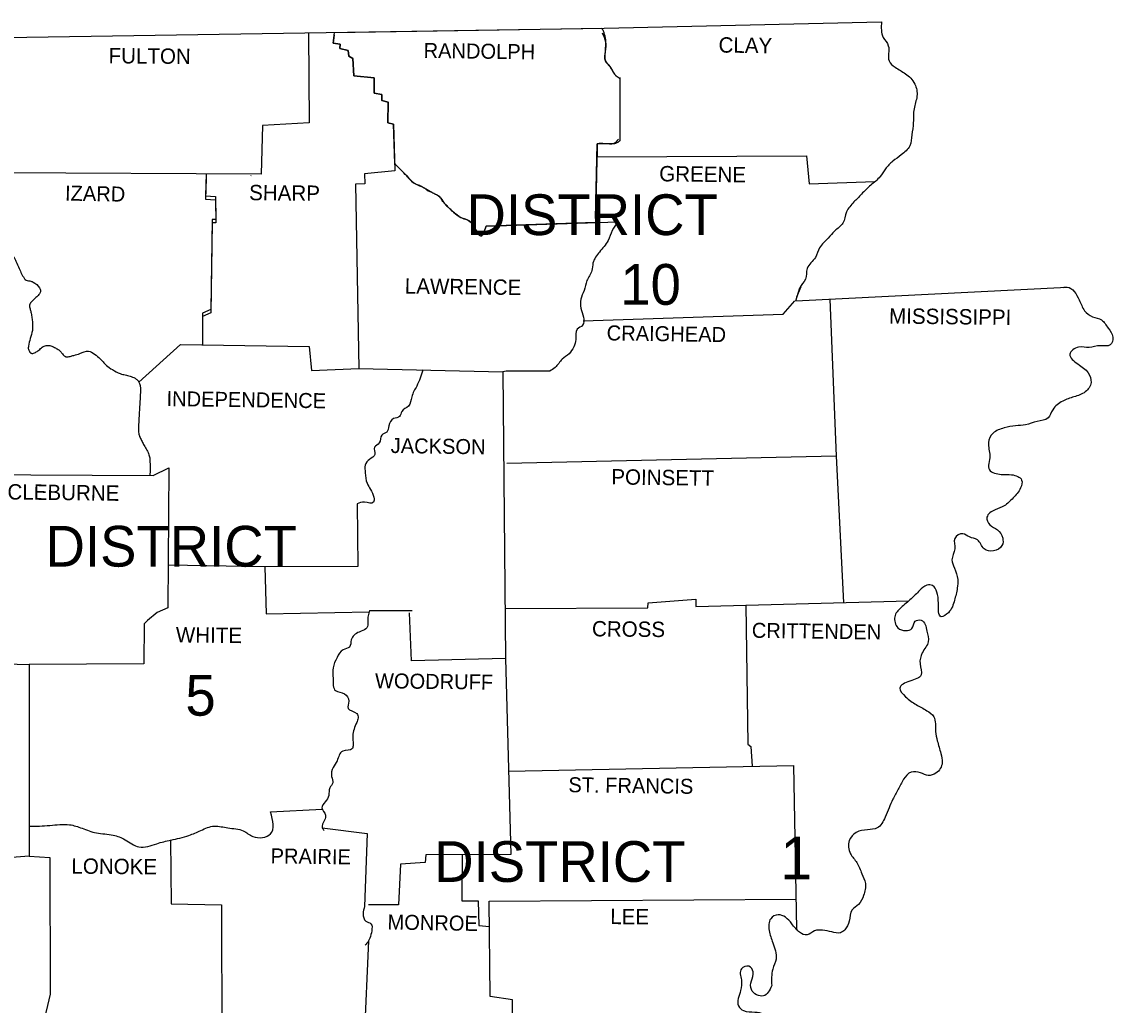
# Model space of a CAD drawing. Extents: x 3046 to 131673, y -8885 to 10756.
# Drawn here: x 28781 to 31768, y 7667 to 10358 of the extents above; entities that cross this region are included whole.
import ezdxf

# ---------------------------------------------------------------- set-up
doc = ezdxf.new("R2010")
doc.units = 0
for name, color, linetype in [('1', 7, 'Continuous'), ('2', 7, 'Continuous'), ('3', 7, 'Continuous')]:
    doc.layers.add(name, color=color, linetype=linetype)

msp = doc.modelspace()

# ---------------------------------------------------------------- linework, layer by layer
at = {"layer": '1'}
for p, q in [((29636.5, 10328.9), (30368.7, 10340.3)), ((30417.5, 10202.4), (30417.5, 10032.6)), ((30898.8, 9593.9), (30910.6, 9630.1)), ((30901.8, 9605.6), (30913.5, 9634)), ((29732.6, 8746.6), (29849, 8746.6))]:
    msp.add_line(p, q, dxfattribs=at)
for points in [[(25766.1, 10313), (27348.2, 10312), (28736.6, 10314.9), (30374.4, 10340.4), (31133.7, 10358)], [(28736.6, 10309.1), (28738.5, 10076.2), (28721.9, 10075.2), (28724.8, 9831.6), (28656.3, 9821.8), (28662.2, 9756.3), (28685.7, 9725.9), (28683.7, 9648.7), (28550.7, 9643.8), (28545.8, 9524.4), (28424.5, 9520.5), (28418.6, 9375.7), (28425.4, 9363.9), (28428.4, 9133), (28637.7, 9119.3), (28634.8, 8603.7), (28801.1, 8598.8), (28801.1, 8074.4), (28670, 8064.6), (28660.3, 7949.2), (28440.1, 7948.2)], [(29565.2, 10327.8), (29567.2, 10081.1), (29440, 10074.3), (29436.1, 9941.2), (28723.5, 9945.1)], [(29801.4, 9970.4), (29798.1, 10078.2), (29782.5, 10081.1), (29783.5, 10137.9), (29765.9, 10142.7), (29765.9, 10159.4), (29745.3, 10162.3), (29745.3, 10204.4), (29689.5, 10210.3), (29686.6, 10257.2), (29675.8, 10264.1), (29673.9, 10279.7), (29651.4, 10284.6), (29652.4, 10296.4), (29632.8, 10299.3), (29636.5, 10328.9)], [(29635.7, 10322.8), (29632.8, 10299.3), (29652.4, 10296.4), (29651.4, 10284.6), (29673.9, 10279.7), (29675.8, 10264.1), (29686.6, 10257.2), (29689.5, 10210.3), (29745.3, 10204.4), (29745.3, 10162.3), (29765.9, 10159.4), (29765.9, 10142.7), (29783.5, 10137.9), (29782.5, 10081.1), (29798.1, 10078.2), (29802.1, 9950), (29718.9, 9942.2), (29719.9, 9914.8), (29694.4, 9913.8), (29703.2, 9408.9), (30097.5, 9400.1), (30104.4, 8615.5), (29847.1, 8608.6), (29842.2, 8740.7)], [(30417.5, 10205.4), (30417.5, 10040)], [(30355.8, 10024.4), (30350.7, 9808.8), (30051.5, 9798.3)], [(30350.9, 9819.9), (30355.8, 10024.4), (30355.8, 9988.2), (30928.2, 9991.1), (30936, 9914.8), (31115.6, 9921.3)], [(29285.6, 9942), (29283.5, 9881.5), (29310.9, 9879.6), (29311.9, 9816.9), (29302.1, 9816.9), (29298.2, 9570.4), (29275.7, 9560.6), (29275.7, 9478.4)], [(29285.5, 9929.5), (29283.5, 9872.7), (29310.9, 9870.7), (29311.9, 9808.1), (29302.1, 9808.1), (29298.2, 9561.6), (29275.7, 9551.8), (29275.7, 9473.7)], [(29407.8, 9936.3), (29408.7, 9937.3)], [(30051.5, 9798.3), (30412.2, 9811)], [(30898.8, 9593.9), (31641.5, 9632)], [(30316.8, 9539.9), (30864.6, 9557.7), (30896.9, 9594.8)], [(30992.5, 9598.7), (31009.4, 9169.2), (31029.3, 8768.4)], [(29101.4, 9371.9), (29215, 9474.5), (29567.2, 9469.6), (29574.1, 9404), (29703.2, 9409)], [(30225.7, 9402.1), (30106.3, 9402.1), (30097.5, 9400.1)], [(31009.4, 9169.2), (30108.3, 9148.7)], [(28637.7, 9119.3), (29140.6, 9116.4), (29183.7, 9136.9), (29180.8, 8754.4), (29151.4, 8741.7), (29125, 8719.2), (29116.2, 8710.4), (29115.2, 8600.8), (28801.1, 8598.8)], [(29698.3, 9039.1), (29700.3, 8866.9), (29445.9, 8865.9), (29181.7, 8870.9)], [(29445.9, 8865.9), (29449.8, 8737.8), (29731.5, 8742.8)], [(30103.2, 8752.4), (30493.8, 8754.4), (30494.8, 8768.1), (30625.9, 8777.9), (30625.9, 8757.3), (31208.7, 8773.3)], [(30762.8, 8761.1), (30767.7, 8380.6), (30776.5, 8374.8), (30779.7, 8320.6)], [(29732.6, 8746.6), (29727.7, 8728.9)], [(30104.4, 8615.5), (30119.1, 8079.3), (29886.2, 8078.3), (29885.2, 8056.8), (29817.7, 8052.9), (29811.8, 7941.3), (29729.7, 7941.3)], [(30112.8, 8307.2), (30893, 8322.9)], [(30893, 8322.9), (30901.2, 7874.7)], [(29461.6, 8195.7), (29603.4, 8202.6)], [(29603.4, 8151.7), (29725.7, 8136), (29718.9, 7936.4)], [(29187.6, 8119.4), (29189.6, 7944.3), (29327.5, 7941.3), (29328.5, 7565.6)], [(28801.1, 8074.4), (28857.9, 8070.5), (28858.9, 7696.7), (28808, 7484.4), (28916.6, 7479.5), (28915.6, 7292.5)], [(29986, 8078.7), (29985, 7952.1), (30030, 7952.1), (30032, 7884.6), (30060.9, 7881.6)], [(30116.1, 7084.2), (30192.4, 7089.1), (30191.5, 7287.8), (30120, 7292.6), (30123.9, 7681.1), (30062.3, 7689.9), (30060.4, 7951.1), (30899.7, 7957)], [(29729.7, 7842.5), (29717.9, 7574.4), (29637.7, 7565.6), (29639.6, 7486.4), (29671.9, 7487.3), (29672.9, 7460), (29716.9, 7455.1), (29718.4, 7407.8)]]:
    msp.add_lwpolyline(points, dxfattribs=at)
for points in [[(30368.7, 10340.3), (30370.6, 10335.8), (30372.5, 10331.2), (30375.5, 10322), (30377.6, 10312.6), (30377.9, 10310.3), (30378.1, 10307.9), (30378.3, 10303.2), (30378.2, 10296.6), (30377.9, 10290), (30377.6, 10283.4), (30377.4, 10276.8), (30377.2, 10273.7), (30376.7, 10264.6), (30376.7, 10258.4), (30376.9, 10255.4), (30377.1, 10253.9), (30377.2, 10253.1), (30377.4, 10252.3), (30378.1, 10249.9), (30378.7, 10248.7), (30379.4, 10247.6), (30381, 10245.5), (30382.8, 10243.6), (30386.7, 10239.7), (30388.5, 10237.8), (30390.1, 10235.7), (30393.2, 10230.6), (30396.3, 10225.4), (30399.4, 10220.2), (30401, 10217.6), (30402.8, 10215.1), (30404.9, 10212.7), (30407.3, 10210.4), (30409.9, 10208.4), (30417.5, 10202.4)], [(31133.7, 10358), (31138.6, 10314.9), (31152.3, 10292.4), (31154.2, 10251.3), (31170.8, 10233.7), (31199.2, 10216.1), (31224.7, 10187.8), (31230.5, 10154.5), (31222.7, 10120.2), (31220.7, 10082.1), (31216.8, 10048.8), (31211, 10018.5), (31187.5, 9994), (31165, 9976.4), (31144.4, 9955.9), (31129.8, 9934.3), (31104.3, 9910.9), (31078.9, 9886.4), (31058.3, 9864.9), (31037.8, 9837.5), (31028, 9807.2), (31005.5, 9785.6), (30987.9, 9766.1), (30964.4, 9739.6), (30952.7, 9713.2), (30930.2, 9682.9), (30925.3, 9653.5), (30910.6, 9630.1), (30909.6, 9626.1)], [(30369.5, 10327.7), (30378.3, 10303.2), (30377.4, 10276.8), (30377.4, 10252.3), (30390.1, 10235.7), (30402.8, 10215.1), (30412.6, 10206.3)], [(30413.6, 10037.1), (30400.8, 10024.4), (30376.4, 10024.4), (30355.8, 10024.4)], [(30417.5, 10032.6), (30415.7, 10030.9), (30413.8, 10029.3), (30409.7, 10026.7), (30405.4, 10025), (30403.1, 10024.5), (30402, 10024.4), (30400.8, 10024.4), (30376.4, 10024.4), (30355.8, 10024.4)], [(30051.5, 9798.3), (30050.1, 9794.1), (30048.4, 9789.2), (30044.5, 9779.4), (30040.3, 9772.4), (30038.1, 9771.1), (30037, 9771.2), (30035.9, 9771.9), (30035.4, 9772.4), (30035, 9772.8), (30034.1, 9773.8), (30032.2, 9776), (30028.6, 9781.2), (30024.9, 9786.9), (30023, 9789.8), (30021.2, 9792.5), (30018.5, 9796.7), (30016, 9800.9), (30013.3, 9805.1), (30010.5, 9809.1), (30007.3, 9812.2), (30003.6, 9814.5), (29995.1, 9817.8), (29986.2, 9820.6), (29978.2, 9824.8), (29972.9, 9828.7), (29967.7, 9832.8), (29962.6, 9837), (29957.6, 9841.4), (29947.2, 9851.5), (29937.1, 9861.9), (29935.2, 9864.2), (29933.4, 9866.6), (29930.2, 9871.7), (29926.7, 9876.5), (29922.4, 9880.5), (29921.1, 9881.4), (29919.7, 9882.2), (29911.2, 9886.6), (29905.5, 9889.3), (29899.9, 9892.3), (29887.2, 9899.6), (29874.5, 9906.9), (29869, 9909.6), (29863.4, 9911.9), (29857.9, 9914.4), (29852.9, 9917.7), (29851.7, 9918.8), (29850.4, 9919.9), (29848, 9922.1), (29843.4, 9926.8), (29834.3, 9936.3), (29817.8, 9953.2), (29801.4, 9970.4)], [(29812.8, 9958.8), (29834.3, 9936.3), (29852.9, 9917.7), (29874.5, 9906.9), (29899.9, 9892.3), (29922.4, 9880.5), (29937.1, 9861.9), (29957.6, 9841.4), (29978.2, 9824.8), (30010.5, 9809.1), (30021.2, 9792.5), (30035.9, 9771.9), (30051.5, 9798.3)], [(30412.2, 9811), (30396.9, 9786.6), (30385.2, 9759.2), (30361.7, 9727.9), (30344.1, 9697.6), (30341.2, 9677), (30327.5, 9649.6), (30319.6, 9622.2), (30310.8, 9598.8), (30310.8, 9574.3), (30317.7, 9549.8), (30315.7, 9527.3), (30301, 9516.6), (30297.1, 9488.2), (30291.3, 9468.6), (30278.5, 9449.1), (30259.9, 9434.4), (30240.4, 9411.9), (30225.7, 9402.1)], [(28685.7, 9725.9), (28695.3, 9722.3), (28705.1, 9720.3), (28715, 9719.5), (28724.8, 9719.1), (28730.9, 9721.1), (28737, 9725.5), (28742.8, 9728.9), (28745.6, 9729.2), (28748.3, 9727.9), (28753.9, 9722.3), (28758.2, 9716), (28761.7, 9709.3), (28764.9, 9702.5), (28773.7, 9682.9), (28780.5, 9668.5), (28784.3, 9661.4), (28786.3, 9657.9), (28788.4, 9654.5), (28793, 9650.8), (28799.2, 9649.2), (28805.8, 9648), (28809, 9647.1), (28811.9, 9645.7), (28829.5, 9630.1), (28832, 9621.6), (28831.4, 9617.2), (28829.5, 9613.4), (28825.8, 9609.4), (28821.8, 9605.6), (28817.7, 9601.8), (28813.9, 9597.8), (28812.1, 9595.9), (28806.5, 9590.4), (28803.5, 9586.5), (28802.6, 9584.4), (28802.1, 9582.1), (28802.4, 9577.5), (28803.5, 9572.9), (28804.9, 9568.2), (28806, 9563.5), (28808.1, 9550.8), (28809.9, 9538.1), (28809.9, 9513.6), (28804.1, 9491.1), (28799.2, 9470.6), (28798.7, 9466.1), (28799.3, 9461.7), (28801.1, 9457.3), (28802.4, 9455.1), (28804.1, 9453), (28806.1, 9451.3), (28808.3, 9450.5), (28813.3, 9451.2), (28822.7, 9455.9), (28827.6, 9459.4), (28832.2, 9463.6), (28837, 9467.7), (28842.2, 9470.6), (28847.2, 9471.8), (28852.5, 9472.3), (28862.8, 9470.6), (28872.8, 9465.7), (28882.4, 9459.8), (28887.6, 9454.9), (28892.2, 9449), (28897.1, 9443.8), (28899.8, 9442.1), (28901.3, 9441.5), (28902.9, 9441.2), (28913.1, 9442.2), (28923.4, 9445.1), (28940.1, 9450), (28963.6, 9456.9), (28980.2, 9448.1), (28994.9, 9436.3), (28999.4, 9431.8), (29003.6, 9427), (29007.9, 9422.2), (29012.5, 9417.7), (29029.1, 9406), (29050.6, 9395.2), (29057.1, 9393.1), (29063.7, 9391.7), (29070.4, 9390.3), (29077.1, 9388.4), (29090.9, 9382.4), (29096.9, 9377.9), (29099.4, 9375.1), (29100.5, 9373.5), (29101.5, 9371.8), (29103.1, 9368.2), (29105.5, 9357.6), (29105.7, 9350.5), (29105.4, 9343.4), (29104.4, 9318.9), (29102.5, 9288.6), (29100.5, 9255.3), (29100.1, 9247.2), (29100.2, 9239.1), (29101.1, 9231), (29102.1, 9227), (29103.5, 9223), (29108.6, 9212), (29114.2, 9201.5), (29121.2, 9189), (29127.9, 9176.1), (29131, 9164.5), (29131.5, 9158.6), (29131.8, 9152.6), (29132.3, 9134.5), (29131, 9116.5)], [(31630.7, 9631), (31641.5, 9632), (31674.7, 9596.8), (31689.4, 9567.4), (31710.9, 9550.8), (31735.4, 9542), (31754, 9519.5), (31766.7, 9495), (31759.8, 9473.5), (31732.4, 9471.6), (31702.1, 9466.7), (31672.8, 9467.6), (31649.3, 9448.1), (31670.8, 9421.7), (31699.2, 9397.2), (31707, 9370.8), (31691.4, 9345.3), (31660, 9331.6), (31629.7, 9319.9), (31602.3, 9296.4), (31589.6, 9273.9), (31559.3, 9264.1), (31528, 9255.3), (31500.6, 9252.4), (31469.3, 9246.5), (31438.9, 9231.8), (31426.2, 9206.4), (31430.1, 9170.2), (31429.1, 9132.1), (31461.4, 9119.3), (31489.8, 9118.4), (31517.2, 9103.7), (31514.3, 9082.2), (31493.7, 9054.8), (31469.3, 9033.2), (31444.8, 9022.5), (31422.3, 9001.9), (31430.1, 8981.4), (31450.7, 8967.7), (31465.3, 8945.2), (31463.4, 8924.6), (31439.9, 8910), (31414.5, 8915.8), (31395.9, 8940.3), (31374.4, 8948.1), (31355.8, 8956.9), (31334.2, 8944.2), (31334.2, 8915.8), (31326.4, 8885.5), (31333.3, 8863), (31342.1, 8831.7), (31341.1, 8808.2), (31333.3, 8774.9), (31316.6, 8740.7), (31297.1, 8729.9), (31289.2, 8767.1), (31285.3, 8797.4), (31273.6, 8815), (31257.9, 8816), (31237.4, 8801.3), (31214.9, 8778.8), (31186.5, 8754.4), (31169.9, 8729.9), (31178.7, 8699.6), (31200.2, 8691.8), (31216.8, 8697.6), (31225.6, 8717.2), (31242.3, 8720.1), (31257.9, 8689.8)], [(29878.8, 9405.1), (29861.7, 9361), (29848, 9331.6), (29839.2, 9306.2), (29820.6, 9291.5), (29814.8, 9277.8), (29798.1, 9272), (29785.4, 9252.4), (29779.5, 9234.8), (29765.9, 9227), (29759, 9205.4), (29746.3, 9193.7), (29747.3, 9174.1), (29732.6, 9160.4), (29720.8, 9144.8), (29720.8, 9123.2), (29725.7, 9094.9), (29735.5, 9078.2), (29744.3, 9056.7), (29743.3, 9043), (29718.9, 9043), (29698.3, 9039.1)], [(29727.7, 8728.9), (29722.8, 8696.7), (29704.2, 8687.9), (29682.7, 8666.3), (29677.8, 8646.8), (29660.2, 8638.9), (29643.6, 8618.4), (29632.8, 8590), (29632.8, 8560.7), (29639.6, 8527.4), (29664.1, 8518.6), (29675.8, 8499), (29673.9, 8478.5), (29697.4, 8464.8), (29701.3, 8453), (29697.4, 8440.3), (29686.6, 8404.1), (29687.6, 8379.7), (29685.6, 8368.9), (29659.2, 8362), (29643.6, 8335.6), (29632.8, 8317), (29628.9, 8292.6), (29631.8, 8275), (29624, 8261.3), (29621, 8240.7), (29611.3, 8223.1), (29602.5, 8206.5), (29612.2, 8186.9), (29609.3, 8173.2), (29603.4, 8151.7), (29608.3, 8144.8)], [(31257.9, 8689.8), (31261.8, 8661.4), (31245.2, 8631.1), (31239.3, 8600.8), (31242.3, 8570.4), (31211, 8553.8), (31183.6, 8534.2), (31199.2, 8510.8), (31228.6, 8489.2), (31257.9, 8472.6), (31276.5, 8456), (31281.4, 8415.9), (31286.3, 8390.4), (31296.1, 8355.2), (31300, 8330.7), (31282.4, 8301.4), (31261.8, 8295.5), (31240.3, 8302.4), (31214.9, 8304.3), (31194.3, 8284.8), (31179.6, 8257.4), (31165, 8230), (31154.2, 8206.5), (31143.4, 8181), (31121.9, 8151.7), (31095.5, 8146.8), (31064.2, 8139), (31045.6, 8117.4), (31048.5, 8081.2), (31066.2, 8056.8), (31079.9, 8026.5), (31089.6, 8000), (31084.7, 7966.8), (31071, 7942.3), (31053.4, 7927.6), (31045.6, 7896.3), (31032.9, 7872.8), (31021.1, 7865), (30997.7, 7867), (30972.2, 7871.9), (30950.7, 7869.9), (30930.2, 7859.1), (30909.6, 7866), (30888.1, 7889.5), (30870.5, 7907.1), (30850.9, 7913.9), (30830.4, 7903.2), (30826.4, 7870.9), (30836.2, 7837.6), (30845, 7792.6), (30836.2, 7765.2), (30833.3, 7720.2)], [(28800.7, 8156.5), (28857.9, 8158.5), (28911.7, 8160.5), (28945.9, 8150.7), (28985.1, 8138), (29031.1, 8132.1), (29063.4, 8119.4), (29101.5, 8099.8), (29150.4, 8108.6), (29188.6, 8118.4), (29238.5, 8131.1), (29270.8, 8144.8), (29308, 8156.6), (29345.1, 8151.7), (29387.2, 8143.9), (29413.6, 8128.2), (29461.6, 8135.1), (29461.6, 8195.7)], [(29718.9, 7936.4), (29715, 7916.9), (29722.8, 7896.3), (29736.5, 7889.5), (29738.5, 7869.9), (29733.6, 7850.3), (29729.7, 7842.5), (29720.8, 7830.8)], [(30833.3, 7720.2), (30810.8, 7691.8), (30777.5, 7709.4), (30777.5, 7732.9), (30782.4, 7757.4), (30770.7, 7773), (30750.1, 7766.2), (30750.1, 7735.9), (30748.2, 7706.5), (30742.3, 7664.4), (30756, 7651.7), (30787.3, 7647.8), (30809.8, 7641.9), (30823.5, 7619.4), (30822.5, 7592), (30811.8, 7565.6), (30796.1, 7544.1), (30771.7, 7536.3), (30752.1, 7549), (30744.3, 7574.4), (30735.5, 7596.9), (30718.8, 7613.6), (30701.2, 7595), (30697.3, 7560.7), (30698.3, 7531.4), (30698.3, 7491.3), (30723.7, 7464.8), (30739.4, 7434.5), (30734.5, 7407.1), (30715.9, 7374.8), (30708.1, 7346.5), (30700.2, 7308.3), (30701.2, 7266.2), (30694.4, 7225.1), (30680.7, 7197.7), (30655.2, 7175.2), (30638.6, 7160.6), (30624.9, 7145.9), (30618, 7116.5), (30613.2, 7096), (30594.6, 7071.5), (30579.9, 7069.6), (30568.1, 7079.4), (30564.2, 7096), (30564.2, 7112.6), (30556.4, 7129.3), (30531.9, 7136.1), (30512.4, 7135.1), (30503.6, 7121.4), (30516.3, 7083.3), (30521.2, 7058.8), (30514.3, 7025.5), (30518.2, 7021.6), (30483, 7003), (30454.7, 7000.1), (30431.2, 6993.3), (30408.7, 6978.6), (30397.9, 6957.1), (30382.2, 6939.4), (30368.6, 6922.8), (30350, 6915), (30329.4, 6918.9), (30302, 6921.8), (30286.4, 6902.3), (30291.3, 6873.9), (30309.8, 6857.3), (30337.2, 6849.4), (30365.6, 6851.4), (30393, 6854.3), (30418.4, 6840.6), (30413.6, 6814.2), (30389.1, 6801.5), (30352.9, 6797.6), (30323.5, 6800.5), (30288.3, 6792.7), (30270.7, 6770.2), (30280.5, 6735.9), (30318.7, 6722.2), (30336.3, 6689.9), (30337.2, 6659.6), (30324.5, 6619.5), (30306.9, 6600.9), (30272.7, 6593.1), (30246.2, 6588.2), (30242.3, 6543.2), (30230.6, 6520.7), (30210, 6513.8), (30180.7, 6528.5), (30163.1, 6535.4), (30141.6, 6545.1), (30114.2, 6561.8), (30093.6, 6558.8), (30099.5, 6515.8), (30101.4, 6513.8), (30124.9, 6481.5), (30148.4, 6456.1), (30159.2, 6425.8)]]:
    msp.add_spline(points, degree=3, dxfattribs=at)

# ---------------------------------------------------------------- texts
msp.add_text('1', height=117.4, dxfattribs=at).set_placement((30856.8, 8010.8))
at = {"layer": '2'}
for s, height, rotation, p in [('CLAY', 42.06, 359.2258, (30687.5, 10273.9)), ('FULTON', 42.06, 359.4996, (29018.3, 10244.5)), ('RANDOLPH', 41.09, 359.2583, (29880.3, 10259.2)), ('GREENE', 42.07, 359.2361, (30525.1, 9921.6)), ('IZARD', 41.08, 358.9258, (28899, 9868.8)), ('SHARP', 42.06, 359.3905, (29402.9, 9869.8)), ('LAWRENCE', 42.07, 359.2678, (29828.9, 9614.2)), ('MISSISSIPPI', 42.062, 359.3097, (31154.2, 9532.2)), ('CRAIGHEAD', 41.09, 359.1159, (30381.3, 9486.2)), ('INDEPENDENCE', 41.081, 359.2187, (29176.9, 9306.2)), ('JACKSON', 41.08, 359.1352, (29790.3, 9178)), ('POINSETT', 42.06, 359.1987, (30394, 9091.9)), ('CLEBURNE', 42.06, 359.2535, (28741.5, 9050.8)), ('WHITE', 42.07, 359.3139, (29202.3, 8659.5)), ('CROSS', 42.06, 359.3839, (30341.2, 8676.1)), ('CRITTENDEN', 41.09, 359.213, (30778.5, 8672.2)), ('WOODRUFF', 41.08, 359.2748, (29747.3, 8534.2)), ('ST. FRANCIS', 41.081, 359.2216, (30276.6, 8249.5)), ('PRAIRIE', 41.09, 359.2116, (29461.6, 8054.8)), ('LONOKE', 42.07, 359.4974, (28916.6, 8026.5)), ('MONROE', 41.08, 359.0331, (29781.5, 7873.8)), ('LEE', 42.07, 359.4327, (30391.1, 7888.5))]:
    msp.add_text(s, height=height, rotation=rotation, dxfattribs=at).set_placement(p)
at = {"layer": '3'}
for s, height, p in [('DISTRICT', 111.54, (29998, 9774.3)), ('10', 111.54, (30418.8, 9583.5)), ('DISTRICT', 111.54, (28846.1, 8866.9)), ('5', 111.5, (29228.7, 8458.9)), ('DISTRICT', 111.54, (29909.7, 8003.9))]:
    msp.add_text(s, height=height, dxfattribs=at).set_placement(p)

doc.saveas('drawing.dxf')
